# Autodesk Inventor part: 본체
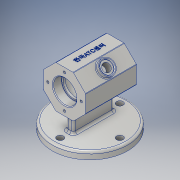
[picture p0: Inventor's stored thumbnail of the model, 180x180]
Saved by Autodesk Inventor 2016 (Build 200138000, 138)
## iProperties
Created: 2021-02
Part Number: 본체
Material: 알루미늄 6061
Document SubType Name: Modeling
Designer: CAD2
Density: 2.7 g/cm^3
Appearance: 알루미늄 - 평지
Mass: 556.744 g
Surface Area: 509.67 cm^2
Volume: 206.202 cm^3
Author: CAD2
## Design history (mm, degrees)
sketch "스케치2"
  geometry: L1 (12.012, 29)-(29, 12.012); L2 (29, 12.012)-(29, -12.012); L3 (29, -12.012)-(12.012, -29); L4 (12.012, -29)-(-12.012, -29); L5 (-12.012, -29)-(-29, -12.012); L6 (-29, -12.012)-(-29, 12.012); L7 (-29, 12.012)-(-12.012, 29); L8 (-12.012, 29)-(12.012, 29); 2 further points
  constraints: 16 end point, 1 coincident, 1 horizontal, 17 other
  dimensions: "d1" = 58 distance between parallel lines of L4 L8
extrude "돌출1" new body sketch "스케치2" stored distance "d2" = 70; taper "d3" = 0 deg
node "작업 평면2"
sketch "스케치3"
  geometry: C1 r 52 at (0, 0); 1 further point
  constraints: 1 centre point, 1 coincident
  dimensions: "d5" = 104 diameter of C1
extrude "돌출2" join sketch "스케치3" distance "d6" = 10; taper "d7" = 0 deg
sketch "스케치4"
  geometry: L1 (5, 28)-(-5, 28); L2 (-5, 28)-(-5, -28); L3 (-5, -28)-(5, -28); L4 (5, -28)-(5, 28); L5 (5, 28)-(-5, -28); L6 (-5, 28)-(5, -28); 1 further point
  constraints: 12 end point, 2 midpoint, 2 parallel, 1 horizontal, 1 perpendicular
  dimensions: "d8" = 10 distance of L3.end L2.end; "d9" = 56 distance of L2.end L1.end
extrude "돌출3" join sketch "스케치4" stored distance "d10" = 10; taper "d11" = 0 deg
sketch "스케치5"
  geometry: L1 (-12.012, 35)-(-12.012, -35) reference; L2 (12.012, 35)-(-12.012, 35) reference; L3 (12.012, 35)-(12.012, -35) reference; L4 (-12.012, -35)-(12.012, -35) reference; L5 (0, 35)-(0, -35); L6 (-62, 52)-(-62, -52) reference; L7 (12.012, 35)-(12.012, -35) reference; L8 (29, 35)-(12.012, 35) reference; L9 (29, 35)-(29, -35) reference; L10 (12.012, -35)-(29, -35) reference; L11 (16, 35)-(16, 23); L12 (16, 23)-(14, 23); L13 (14, 23)-(14, 20); L14 (14, 20)-(22, 20); L15 (22, 20)-(22, -20); L16 (22, -20)-(14, -20); L17 (14, -20)-(14, -23); L18 (14, -23)-(16, -23); L19 (16, -23)-(16, -35); L20 (16, 35)-(0, 35); L21 (12.012, 35)-(-12.012, 35) reference; L22 (16, -35)-(0, -35); L23 (12.012, -35)-(29, -35) reference; 1 further point
  constraints: 24 end point, 7 perpendicular, 6 point on line, 4 collinear, 2 midpoint, 1 vertical
  dimensions: "d12" = 62 distance between parallel lines of L6 L5; "d13" = 28 diameter of L13 L5; "d14" = 32 diameter of L11 L5; "d15" = 44 diameter of L15 L5; "d16" = 12 distance of L11.start L11.end; "d17" = 40 distance between parallel lines of L16 L14
revolve "회전1" sketch "스케치5" stored, may be unused: angle "d18" = 90 deg
sketch "스케치6" dims "d19" = 46
  geometry: L1 (0, 0)-(-23, 0); 2 further points
  constraints: 2 coincident, 2 end point, 1 horizontal, 1 horizontal alignment, 2 other
hole "구멍1" sketch "스케치6" diameter "d22" = 3.242; stored, may be unused: countersink angle "d26" = 90 deg, drill point angle "d28" = 118 deg; dims "d23" = 8, "d24" = 4, "d25" = 2, "d27" = 10
sketch "스케치7"
  geometry: C1 r 10 at (-12.012, 35); 1 further point
  constraints: 1 centre point, 1 coincident
  dimensions: "d21" = 20 diameter of C1
extrude "돌출4" join sketch "스케치7" distance "d32" = 5; taper "d33" = 0 deg
sketch "스케치8"
  geometry: C1 r 8 at (0, 0); 1 further point
  constraints: 1 centre point, 1 coincident
  dimensions: "d34" = 16 diameter of C1
extrude "돌출5" cut sketch "스케치8" distance "d35" = 2; taper "d36" = 0 deg
sketch "스케치9"
  geometry: 2 further points
  constraints: 1 coincident
hole "구멍2" sketch "스케치9" at (0, 0) diameter "d37" = 10.917; stored, may be unused: countersink angle "d41" = 90 deg, drill point angle "d43" = 118 deg; dims "d38" = 24, "d39" = 4, "d40" = 2, "d42" = 25
node "작업 평면5"
sketch "스케치10"
  geometry: 2 further points
  constraints: 1 other
feature "엠보싱1" sketch "스케치10" dims "d8" = 10, "d9" = 56, "d45" = 0.5, "d46" = 0
sketch "스케치11" dims "d47" = 82
  geometry: 3 further points
  constraints: 1 coincident, 1 vertical alignment, 2 other
hole "구멍3" sketch "스케치11" at (0, -41) diameter "d48" = 9; stored, may be unused: countersink angle "d52" = 90 deg, drill point angle "d54" = 118 deg; dims "d49" = 24, "d50" = 4, "d51" = 2, "d53" = 25
fillet "모깎기1" dims "d58" = 0.3
fillet "모깎기2" dims "d59" = 1
fillet "모깎기3" dims "d60" = 1
fillet "모깎기4" dims "d61" = 3
fillet "모깎기5" dims "d62" = 3
fillet "모깎기6" dims "d63" = 3
fillet "모깎기7" dims "d64" = 3
chamfer "모따기1" distance "d65" = 1; stored, may be unused: second distance "d66" = 2, angle "d67" = 45 deg
chamfer "모따기2" distance "d68" = 1; stored, may be unused: second distance "d69" = 2, angle "d70" = 45 deg
node "솔리드1"
pattern_circular "원형 패턴1" dims angle "d30" = 360 deg
mirror "대칭1"
pattern_circular "원형 패턴2" dims angle "d56" = 360 deg
node "투영된 루프1"
node "투영된 루프2"
other parameters: "d4" = -62, "d44" = 30.25
